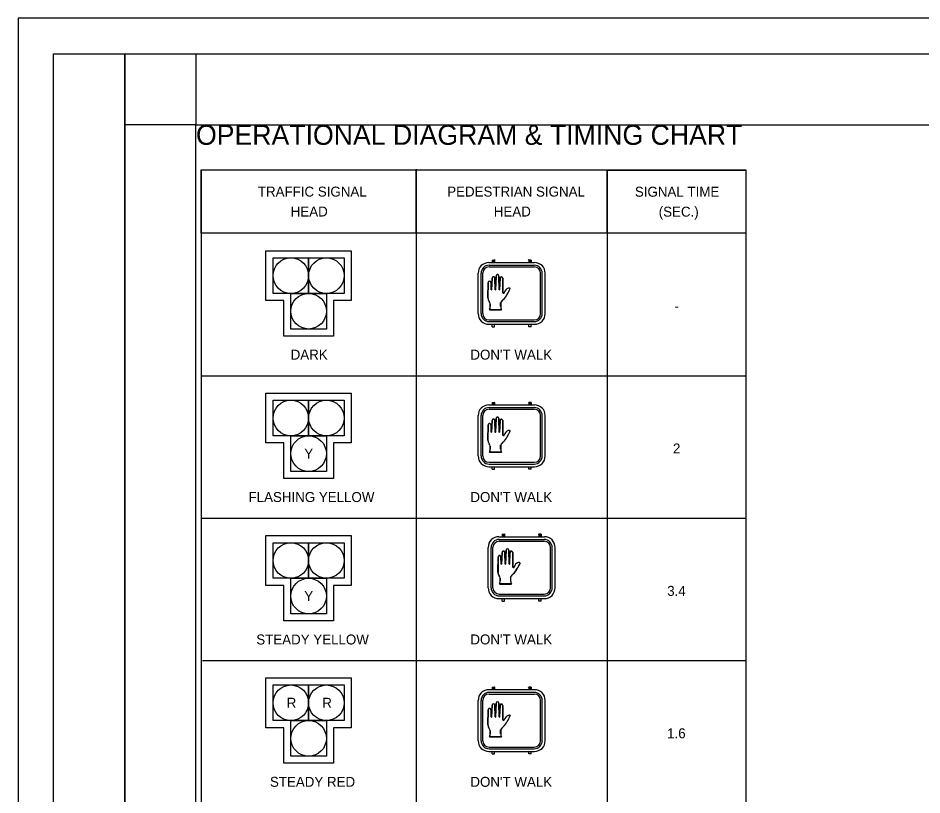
# Model space of a CAD drawing. Extents: x 59.9 to 93.9, y -8.4 to 13.6.
# Drawn here: x 59.95 to 72.65, y 2.7 to 13.61 of the extents above; entities that cross this region are included whole.
import ezdxf

# ---------------------------------------------------------------- set-up
doc = ezdxf.new("R2010")
doc.units = 0
for name, color, linetype in [('Default', 7, 'Continuous'), ('SG_P_Text', 7, 'Continuous'), ('SH_Border', 7, 'Continuous'), ('SH_Cut_Line', 7, 'Continuous'), ('SH_Data', 7, 'Continuous'), ('SH_Named_Boundary', 7, 'Continuous'), ('SH_Text', 7, 'Continuous')]:
    doc.layers.add(name, color=color, linetype=linetype)

# ---------------------------------------------------------------- blocks, each defined once
blk = doc.blocks.new('HAND')
at = {"layer": 'Default'}
for points in [[(-0.0196, 0.1047), (-0.0197, 0.1045), (-0.0167, 0.1665), (-0.0167, 0.1665)], [(-0.0022, 0.1665), (-0.0022, 0.1665), (-0.0014, 0.105), (-0.0014, 0.105)], [(0.0005, 0.1047), (0.0004, 0.1045), (0.004, 0.1776), (0.004, 0.1776)], [(0.0186, 0.1776), (0.0186, 0.1776), (0.0199, 0.105), (0.0199, 0.105)], [(0.0218, 0.1047), (0.0218, 0.1045), (0.0247, 0.1659), (0.0247, 0.1659)], [(0.0392, 0.1659), (0.0392, 0.1659), (0.0402, 0.0888), (0.0402, 0.0888)], [(-0.0387, 0.0626), (-0.0387, 0.0626), (-0.0372, 0.143), (-0.0372, 0.143)], [(-0.0227, 0.143), (-0.0227, 0.143), (-0.0215, 0.105), (-0.0215, 0.105)], [(0.0477, 0.089), (0.0477, 0.089)], [(-0.032, 0.0432), (-0.032, 0.0432)], [(-0.0271, 0.0154), (-0.0271, 0.0154), (-0.0271, 0.0308), (-0.0271, 0.0308)], [(0.0284, 0.0364), (0.0284, 0.0364), (0.0284, 0.0154), (0.0284, 0.0154)], [(0.0327, -0.0008), (-0.0313, -0.0008), (-0.0313, -0.0008)], [(0.0327, -0.0008), (0.0327, -0.0008)]]:
    blk.add_lwpolyline(points, dxfattribs=at)
for centre, radius, start, end in [((-0.03, 0.143), 0.00726, 0, 180), ((-0.0094, 0.1665), 0.00726, 0, 180), ((0.0113, 0.1776), 0.00726, 0, 180), ((0.032, 0.1659), 0.00726, 0, 180), ((-0.0206, 0.1048), 0.000943, 167.1401, 358.6099), ((-0.0005, 0.1048), 0.000943, 167.1401, 358.6099), ((0.0208, 0.1048), 0.000943, 167.1401, 358.6099), ((-0.1141, 0.1925), 0.2098, 318.2058, 337.3712), ((0.078, 0.0836), 0.0308, 107.2466, 169.8826), ((0.073, 0.1019), 0.0119, 56.229, 110.2726), ((-0.011, 0.0613), 0.0278, 177.3964, 220.6574), ((0.0742, 0.0112), 0.0523, 127.5194, 151.0809), ((0.0439, 0.0907), 0.00414, 208.0703, 335.996), ((-0.0476, 0.0298), 0.0205, 2.7749, 40.7212), ((-0.0593, 0.0151), 0.0322, 330.2887, 0.5181), ((0.0606, 0.0151), 0.0322, 179.4819, 209.7113)]:
    blk.add_arc(centre, radius, start, end, dxfattribs=at)

msp = doc.modelspace()

# ---------------------------------------------------------------- linework, layer by layer
at = {"layer": 'SG_P_Text'}
for p, q in [((62.52, 11.475), (70.174, 11.475)), ((62.52, 11.475), (62.52, -3.417)), ((65.54, 11.482), (65.54, -3.417)), ((68.226, 11.471), (68.226, -3.417)), ((70.171, 11.475), (70.171, -3.417)), ((62.534, 8.583), (70.178, 8.583)), ((62.523, 6.582), (70.178, 6.583)), ((62.541, 4.583), (70.177, 4.583))]:
    msp.add_line(p, q, dxfattribs=at)
for points in [[(62.52, 11.475), (65.54, 11.475), (65.54, 10.583), (62.52, 10.583)], [(65.54, 11.475), (68.226, 11.475), (68.226, 10.583), (65.54, 10.583)], [(68.226, 11.471), (70.172, 11.471), (70.172, 10.583), (68.226, 10.583)], [(63.43, 10.339), (64.63, 10.339), (64.63, 9.639), (64.38, 9.639), (64.38, 9.139), (63.68, 9.139), (63.68, 9.639), (63.43, 9.639)], [(63.53, 10.239), (64.03, 10.239), (64.03, 9.739), (63.53, 9.739)], [(64.03, 10.239), (64.53, 10.239), (64.53, 9.739), (64.03, 9.739)], [(63.78, 9.739), (64.28, 9.739), (64.28, 9.239), (63.78, 9.239)], [(63.43, 8.339), (64.63, 8.339), (64.63, 7.639), (64.38, 7.639), (64.38, 7.139), (63.68, 7.139), (63.68, 7.639), (63.43, 7.639)], [(63.53, 8.239), (64.03, 8.239), (64.03, 7.739), (63.53, 7.739)], [(64.03, 8.239), (64.53, 8.239), (64.53, 7.739), (64.03, 7.739)], [(63.78, 7.739), (64.28, 7.739), (64.28, 7.239), (63.78, 7.239)], [(63.43, 6.338), (64.63, 6.338), (64.63, 5.638), (64.38, 5.638), (64.38, 5.138), (63.68, 5.138), (63.68, 5.638), (63.43, 5.638)], [(63.53, 6.238), (64.03, 6.238), (64.03, 5.738), (63.53, 5.738)], [(64.03, 6.238), (64.53, 6.238), (64.53, 5.738), (64.03, 5.738)], [(63.78, 5.738), (64.28, 5.738), (64.28, 5.238), (63.78, 5.238)], [(63.43, 4.339), (64.63, 4.339), (64.63, 3.639), (64.38, 3.639), (64.38, 3.139), (63.68, 3.139), (63.68, 3.639), (63.43, 3.639)], [(63.53, 4.239), (64.03, 4.239), (64.03, 3.739), (63.53, 3.739)], [(64.03, 4.239), (64.53, 4.239), (64.53, 3.739), (64.03, 3.739)], [(63.78, 3.739), (64.28, 3.739), (64.28, 3.239), (63.78, 3.239)]]:
    msp.add_lwpolyline(points, close=True, dxfattribs=at)
for centre in [(63.78, 9.989), (64.28, 9.989), (64.03, 9.489), (63.78, 7.989), (64.28, 7.989), (64.03, 7.489), (63.78, 5.988), (64.28, 5.988), (64.03, 5.488), (63.78, 3.989), (64.28, 3.989), (64.03, 3.489)]:
    msp.add_circle(centre, 0.25, dxfattribs=at)
at = {"layer": 'SH_Border'}
for points in [[(60.448, 13.106), (61.448, 13.106), (61.448, -7.894), (60.448, -7.894)], [(61.448, 13.106), (93.448, 13.106), (93.448, -7.894), (61.448, -7.894)]]:
    msp.add_lwpolyline(points, close=True, dxfattribs=at)
at = {"layer": 'SH_Cut_Line'}
msp.add_lwpolyline([(59.948, -8.394), (93.948, -8.394), (93.948, 13.606), (59.948, 13.606)], close=True, dxfattribs=at)
at = {"layer": 'SH_Data'}
for p, q in [((66.563, 10.174), (66.606, 10.174)), ((66.618, 10.185), (66.603, 10.171)), ((66.603, 10.171), (66.605, 10.169)), ((66.62, 10.184), (66.605, 10.169)), ((66.607, 10.208), (66.607, 10.175)), ((66.607, 10.208), (66.641, 10.208)), ((66.61, 10.174), (67.156, 10.174)), ((66.631, 10.198), (66.645, 10.213)), ((66.633, 10.196), (66.647, 10.211)), ((66.643, 10.207), (66.643, 10.174)), ((66.647, 10.211), (66.645, 10.213)), ((67.121, 10.213), (67.119, 10.211)), ((67.133, 10.196), (67.119, 10.211)), ((67.135, 10.198), (67.121, 10.213)), ((67.123, 10.207), (67.123, 10.174)), ((67.159, 10.208), (67.125, 10.208)), ((67.146, 10.184), (67.161, 10.169)), ((67.148, 10.185), (67.163, 10.171)), ((67.159, 10.208), (67.159, 10.175)), ((67.16, 10.174), (67.203, 10.174)), ((67.163, 10.171), (67.161, 10.169)), ((66.566, 10.136), (67.2, 10.136)), ((66.566, 10.111), (67.2, 10.111)), ((66.412, 9.456), (66.412, 10.022)), ((66.453, 9.456), (66.453, 10.022)), ((66.477, 9.755), (66.477, 10.022)), ((67.289, 9.755), (67.289, 10.022)), ((67.313, 9.456), (67.313, 10.022)), ((67.354, 9.456), (67.354, 10.022)), ((66.477, 9.456), (66.477, 9.755)), ((67.289, 9.456), (67.289, 9.755)), ((66.563, 9.305), (67.203, 9.305)), ((66.566, 9.367), (67.2, 9.367)), ((66.566, 9.343), (67.2, 9.343)), ((66.607, 9.27), (66.607, 9.305)), ((66.607, 9.27), (66.643, 9.27)), ((66.643, 9.27), (66.643, 9.305)), ((67.123, 9.27), (67.123, 9.305)), ((67.159, 9.27), (67.123, 9.27)), ((67.159, 9.27), (67.159, 9.305)), ((66.563, 8.174), (66.606, 8.174)), ((66.566, 8.136), (67.2, 8.136)), ((66.618, 8.185), (66.603, 8.171)), ((66.603, 8.171), (66.605, 8.169)), ((66.62, 8.184), (66.605, 8.169)), ((66.607, 8.208), (66.607, 8.175)), ((66.607, 8.208), (66.641, 8.208)), ((66.61, 8.174), (67.156, 8.174)), ((66.631, 8.198), (66.645, 8.213)), ((66.633, 8.196), (66.647, 8.211)), ((66.643, 8.207), (66.643, 8.174)), ((66.647, 8.211), (66.645, 8.213)), ((67.121, 8.213), (67.119, 8.211)), ((67.133, 8.196), (67.119, 8.211)), ((67.135, 8.198), (67.121, 8.213)), ((67.123, 8.207), (67.123, 8.174)), ((67.159, 8.208), (67.125, 8.208)), ((67.146, 8.184), (67.161, 8.169)), ((67.148, 8.185), (67.163, 8.171)), ((67.159, 8.208), (67.159, 8.175)), ((67.16, 8.174), (67.203, 8.174)), ((67.163, 8.171), (67.161, 8.169)), ((66.412, 7.456), (66.412, 8.022)), ((66.453, 7.456), (66.453, 8.022)), ((66.477, 7.755), (66.477, 8.022)), ((66.566, 8.111), (67.2, 8.111)), ((67.289, 7.755), (67.289, 8.022)), ((67.313, 7.456), (67.313, 8.022)), ((67.354, 7.456), (67.354, 8.022)), ((66.477, 7.456), (66.477, 7.755)), ((67.289, 7.456), (67.289, 7.755)), ((66.566, 7.367), (67.2, 7.367)), ((66.563, 7.305), (67.203, 7.305)), ((66.566, 7.343), (67.2, 7.343)), ((66.607, 7.27), (66.607, 7.305)), ((66.607, 7.27), (66.643, 7.27)), ((66.643, 7.27), (66.643, 7.305)), ((67.123, 7.27), (67.123, 7.305)), ((67.159, 7.27), (67.123, 7.27)), ((67.159, 7.27), (67.159, 7.305)), ((66.748, 6.356), (66.748, 6.322)), ((66.748, 6.356), (66.781, 6.356)), ((66.771, 6.346), (66.786, 6.36)), ((66.773, 6.344), (66.788, 6.359)), ((66.784, 6.355), (66.784, 6.321)), ((66.788, 6.359), (66.786, 6.36)), ((67.261, 6.36), (67.259, 6.359)), ((67.274, 6.344), (67.259, 6.359)), ((67.276, 6.346), (67.261, 6.36)), ((67.263, 6.355), (67.263, 6.321)), ((67.299, 6.356), (67.266, 6.356)), ((67.299, 6.356), (67.299, 6.322)), ((66.703, 6.321), (66.747, 6.321)), ((66.707, 6.283), (67.34, 6.283)), ((66.707, 6.259), (67.34, 6.259)), ((66.758, 6.333), (66.744, 6.318)), ((66.744, 6.318), (66.746, 6.317)), ((66.76, 6.331), (66.746, 6.317)), ((66.75, 6.321), (67.297, 6.321)), ((67.287, 6.331), (67.301, 6.317)), ((67.288, 6.333), (67.303, 6.318)), ((67.3, 6.321), (67.343, 6.321)), ((67.303, 6.318), (67.301, 6.317)), ((66.552, 5.604), (66.552, 6.17)), ((66.593, 5.604), (66.593, 6.17)), ((66.618, 5.903), (66.618, 6.17)), ((67.429, 5.903), (67.429, 6.17)), ((67.453, 5.604), (67.453, 6.17)), ((67.495, 5.604), (67.495, 6.17)), ((66.618, 5.604), (66.618, 5.903)), ((67.429, 5.604), (67.429, 5.903)), ((66.707, 5.515), (67.34, 5.515)), ((66.707, 5.491), (67.34, 5.491)), ((66.703, 5.453), (67.343, 5.453)), ((66.748, 5.418), (66.748, 5.453)), ((66.748, 5.418), (66.784, 5.418)), ((66.784, 5.418), (66.784, 5.453)), ((67.263, 5.418), (67.263, 5.453)), ((67.299, 5.418), (67.263, 5.418)), ((67.299, 5.418), (67.299, 5.453)), ((66.607, 4.208), (66.607, 4.175)), ((66.607, 4.208), (66.641, 4.208)), ((66.631, 4.198), (66.645, 4.213)), ((66.633, 4.196), (66.647, 4.211)), ((66.643, 4.207), (66.643, 4.174)), ((66.647, 4.211), (66.645, 4.213)), ((67.121, 4.213), (67.119, 4.211)), ((67.133, 4.196), (67.119, 4.211)), ((67.135, 4.198), (67.121, 4.213)), ((67.123, 4.207), (67.123, 4.174)), ((67.159, 4.208), (67.125, 4.208)), ((67.159, 4.208), (67.159, 4.175)), ((66.563, 4.174), (66.606, 4.174)), ((66.566, 4.136), (67.2, 4.136)), ((66.566, 4.111), (67.2, 4.111)), ((66.618, 4.185), (66.603, 4.171)), ((66.603, 4.171), (66.605, 4.169)), ((66.62, 4.184), (66.605, 4.169)), ((66.61, 4.174), (67.156, 4.174)), ((67.146, 4.184), (67.161, 4.169)), ((67.148, 4.185), (67.163, 4.171)), ((67.16, 4.174), (67.203, 4.174)), ((67.163, 4.171), (67.161, 4.169)), ((66.412, 3.456), (66.412, 4.022)), ((66.453, 3.456), (66.453, 4.022)), ((66.477, 3.755), (66.477, 4.022)), ((67.289, 3.755), (67.289, 4.022)), ((67.313, 3.456), (67.313, 4.022)), ((67.354, 3.456), (67.354, 4.022)), ((66.477, 3.456), (66.477, 3.755)), ((67.289, 3.456), (67.289, 3.755)), ((66.563, 3.305), (67.203, 3.305)), ((66.566, 3.367), (67.2, 3.367)), ((66.566, 3.343), (67.2, 3.343)), ((66.607, 3.27), (66.607, 3.305)), ((66.643, 3.27), (66.643, 3.305)), ((67.123, 3.27), (67.123, 3.305)), ((67.159, 3.27), (67.159, 3.305)), ((66.607, 3.27), (66.643, 3.27)), ((67.159, 3.27), (67.123, 3.27))]:
    msp.add_line(p, q, dxfattribs=at)
for points in [[(66.609, 9.954), (66.601, 9.79), (66.601, 9.79)], [(66.649, 9.79), (66.647, 9.954), (66.647, 9.954)], [(66.664, 9.983), (66.654, 9.79), (66.654, 9.79)], [(66.706, 9.79), (66.702, 9.983)], [(66.719, 9.952), (66.711, 9.79), (66.711, 9.79)], [(66.76, 9.747), (66.757, 9.952)], [(66.554, 9.891), (66.55, 9.678)], [(66.596, 9.79), (66.593, 9.891), (66.593, 9.891)], [(66.601, 9.789), (66.601, 9.789), (66.601, 9.789)], [(66.654, 9.789), (66.654, 9.789), (66.654, 9.789)], [(66.711, 9.789), (66.711, 9.789), (66.711, 9.789)], [(66.779, 9.748), (66.779, 9.748)], [(66.568, 9.627), (66.568, 9.627)], [(66.581, 9.594), (66.581, 9.553)], [(66.728, 9.553), (66.728, 9.609)], [(66.57, 9.51), (66.74, 9.51)], [(66.554, 7.891), (66.55, 7.678)], [(66.596, 7.79), (66.593, 7.891), (66.593, 7.891)], [(66.609, 7.954), (66.601, 7.79), (66.601, 7.79)], [(66.649, 7.79), (66.647, 7.954), (66.647, 7.954)], [(66.664, 7.983), (66.654, 7.79), (66.654, 7.79)], [(66.706, 7.79), (66.702, 7.983)], [(66.719, 7.952), (66.711, 7.79), (66.711, 7.79)], [(66.76, 7.747), (66.757, 7.952)], [(66.601, 7.789), (66.601, 7.789), (66.601, 7.789)], [(66.654, 7.789), (66.654, 7.789), (66.654, 7.789)], [(66.711, 7.789), (66.711, 7.789), (66.711, 7.789)], [(66.779, 7.748), (66.779, 7.748)], [(66.568, 7.627), (66.568, 7.627)], [(66.57, 7.51), (66.74, 7.51)], [(66.581, 7.594), (66.581, 7.553)], [(66.728, 7.553), (66.728, 7.609)], [(66.749, 6.101), (66.741, 5.937), (66.741, 5.937)], [(66.79, 5.938), (66.787, 6.101), (66.788, 6.101)], [(66.804, 6.131), (66.795, 5.937), (66.795, 5.937)], [(66.846, 5.938), (66.843, 6.131)], [(66.859, 6.1), (66.851, 5.937), (66.851, 5.937)], [(66.9, 5.895), (66.897, 6.1)], [(66.695, 6.039), (66.691, 5.826)], [(66.736, 5.938), (66.733, 6.039), (66.733, 6.039)], [(66.741, 5.937), (66.741, 5.937), (66.741, 5.937)], [(66.795, 5.937), (66.795, 5.937), (66.794, 5.937)], [(66.851, 5.937), (66.851, 5.937), (66.851, 5.937)], [(66.92, 5.896), (66.92, 5.896)], [(66.708, 5.774), (66.708, 5.774)], [(66.721, 5.741), (66.721, 5.701)], [(66.869, 5.701), (66.869, 5.756)], [(66.71, 5.657), (66.88, 5.657)], [(66.609, 3.954), (66.601, 3.79), (66.601, 3.79)], [(66.649, 3.79), (66.647, 3.954), (66.647, 3.954)], [(66.664, 3.983), (66.654, 3.79), (66.654, 3.79)], [(66.706, 3.79), (66.702, 3.983)], [(66.719, 3.952), (66.711, 3.79), (66.711, 3.79)], [(66.76, 3.747), (66.757, 3.952)], [(66.554, 3.891), (66.55, 3.678)], [(66.596, 3.79), (66.593, 3.891), (66.593, 3.891)], [(66.601, 3.789), (66.601, 3.789), (66.601, 3.789)], [(66.654, 3.789), (66.654, 3.789), (66.654, 3.789)], [(66.711, 3.789), (66.711, 3.789), (66.711, 3.789)], [(66.779, 3.748), (66.779, 3.748)], [(66.568, 3.627), (66.568, 3.627)], [(66.581, 3.594), (66.581, 3.553)], [(66.728, 3.553), (66.728, 3.609)], [(66.57, 3.51), (66.74, 3.51)]]:
    msp.add_lwpolyline(points, dxfattribs=at)
for centre in [(66.625, 10.191), (67.141, 10.191), (66.625, 8.191), (67.141, 8.191), (66.766, 6.338), (67.281, 6.338), (66.625, 4.191), (67.141, 4.191)]:
    msp.add_circle(centre, 0.00918, dxfattribs=at)
for centre, radius, start, end in [((66.563, 10.022), 0.151, 90, 180), ((67.203, 10.022), 0.151, 360, 90), ((66.566, 10.022), 0.113, 90, 180), ((66.566, 10.022), 0.089, 90, 180), ((67.2, 10.022), 0.113, 360, 90), ((67.2, 10.022), 0.089, 360, 90), ((66.573, 9.891), 0.0193, 0, 180), ((66.628, 9.954), 0.0193, 0, 180), ((66.683, 9.983), 0.0193, 360, 180), ((66.738, 9.952), 0.0193, 0, 180), ((66.598, 9.79), 0.0025, 167.1401, 346.8691), ((66.598, 9.79), 0.0025, 347.3062, 358.6099), ((66.652, 9.79), 0.0025, 167.1401, 346.5951), ((66.652, 9.79), 0.0025, 351.0095, 358.6099), ((66.708, 9.79), 0.0025, 167.1401, 347.1404), ((66.708, 9.79), 0.0025, 349.4624, 358.6099), ((66.35, 10.023), 0.557, 318.2058, 337.3712), ((66.86, 9.734), 0.0817, 107.2466, 169.8826), ((66.847, 9.782), 0.0315, 56.229, 110.2726), ((66.624, 9.675), 0.0738, 177.3964, 220.6574), ((66.85, 9.542), 0.139, 127.5194, 151.0809), ((66.769, 9.753), 0.011, 208.0703, 335.996), ((66.527, 9.591), 0.0544, 2.7749, 40.7212), ((66.496, 9.552), 0.0855, 330.2887, 0.5181), ((66.814, 9.552), 0.0855, 179.4819, 209.7113), ((66.563, 9.456), 0.151, 180, 270), ((66.566, 9.456), 0.113, 180, 270), ((66.566, 9.456), 0.089, 180, 270), ((67.2, 9.456), 0.113, 270, 360), ((67.2, 9.456), 0.089, 270, 360), ((67.203, 9.456), 0.151, 270, 360), ((66.563, 8.022), 0.151, 90, 180), ((66.566, 8.022), 0.113, 90, 180), ((67.2, 8.022), 0.113, 360, 90), ((67.203, 8.022), 0.151, 360, 90), ((66.566, 8.022), 0.089, 90, 180), ((66.683, 7.983), 0.0193, 360, 180), ((67.2, 8.022), 0.089, 360, 90), ((66.573, 7.891), 0.0193, 0, 180), ((66.628, 7.954), 0.0193, 0, 180), ((66.738, 7.952), 0.0193, 0, 180), ((66.598, 7.79), 0.0025, 167.1401, 346.8691), ((66.598, 7.79), 0.0025, 347.3062, 358.6099), ((66.652, 7.79), 0.0025, 167.1401, 346.5951), ((66.652, 7.79), 0.0025, 351.0095, 358.6099), ((66.708, 7.79), 0.0025, 167.1401, 347.1404), ((66.708, 7.79), 0.0025, 349.4624, 358.6099), ((66.769, 7.753), 0.011, 208.0703, 335.996), ((66.35, 8.023), 0.557, 318.2058, 337.3712), ((66.86, 7.734), 0.0817, 107.2466, 169.8826), ((66.847, 7.782), 0.0315, 56.229, 110.2726), ((66.624, 7.675), 0.0738, 177.3964, 220.6574), ((66.527, 7.591), 0.0544, 2.7749, 40.7212), ((66.85, 7.542), 0.139, 127.5194, 151.0809), ((66.496, 7.552), 0.0855, 330.2887, 0.5181), ((66.814, 7.552), 0.0855, 179.4819, 209.7113), ((66.563, 7.456), 0.151, 180, 270), ((66.566, 7.456), 0.113, 180, 270), ((66.566, 7.456), 0.089, 180, 270), ((67.2, 7.456), 0.113, 270, 360), ((67.2, 7.456), 0.089, 270, 360), ((67.203, 7.456), 0.151, 270, 360), ((66.703, 6.17), 0.151, 90, 180), ((66.707, 6.17), 0.113, 90, 180), ((66.707, 6.17), 0.089, 90, 180), ((67.34, 6.17), 0.113, 360, 90), ((67.34, 6.17), 0.089, 360, 90), ((67.343, 6.17), 0.151, 360, 90), ((66.768, 6.101), 0.0193, 0, 180), ((66.823, 6.131), 0.0193, 360, 180), ((66.878, 6.1), 0.0193, 0, 180), ((66.714, 6.039), 0.0193, 0, 180), ((66.739, 5.937), 0.0025, 167.1401, 346.8691), ((66.739, 5.937), 0.0025, 347.3062, 358.6099), ((66.792, 5.937), 0.0025, 167.1401, 346.5951), ((66.792, 5.937), 0.0025, 351.0095, 358.6099), ((66.849, 5.937), 0.0025, 167.1401, 347.1404), ((66.849, 5.937), 0.0025, 349.4624, 358.6099), ((66.91, 5.9), 0.011, 208.0703, 335.996), ((66.491, 6.17), 0.557, 318.2058, 337.3712), ((67, 5.881), 0.0817, 107.2466, 169.8826), ((66.987, 5.93), 0.0315, 56.229, 110.2726), ((66.764, 5.822), 0.0738, 177.3964, 220.6574), ((66.667, 5.739), 0.0544, 2.7749, 40.7212), ((66.99, 5.689), 0.139, 127.5194, 151.0809), ((66.703, 5.604), 0.151, 180, 270), ((66.707, 5.604), 0.113, 180, 270), ((66.707, 5.604), 0.089, 180, 270), ((66.636, 5.7), 0.0855, 330.2887, 0.5181), ((66.954, 5.7), 0.0855, 179.4819, 209.7113), ((67.34, 5.604), 0.113, 270, 360), ((67.34, 5.604), 0.089, 270, 360), ((67.343, 5.604), 0.151, 270, 360), ((66.563, 4.022), 0.151, 90, 180), ((66.566, 4.022), 0.113, 90, 180), ((66.566, 4.022), 0.089, 90, 180), ((67.2, 4.022), 0.113, 360, 90), ((67.2, 4.022), 0.089, 360, 90), ((67.203, 4.022), 0.151, 360, 90), ((66.628, 3.954), 0.0193, 0, 180), ((66.683, 3.983), 0.0193, 360, 180), ((66.738, 3.952), 0.0193, 0, 180), ((66.573, 3.891), 0.0193, 0, 180), ((66.86, 3.734), 0.0817, 107.2466, 169.8826), ((66.847, 3.782), 0.0315, 56.229, 110.2726), ((66.598, 3.79), 0.0025, 167.1401, 346.8691), ((66.598, 3.79), 0.0025, 347.3062, 358.6099), ((66.652, 3.79), 0.0025, 167.1401, 346.5951), ((66.652, 3.79), 0.0025, 351.0095, 358.6099), ((66.708, 3.79), 0.0025, 167.1401, 347.1404), ((66.708, 3.79), 0.0025, 349.4624, 358.6099), ((66.769, 3.753), 0.011, 208.0703, 335.996), ((66.35, 4.023), 0.557, 318.2058, 337.3712), ((66.624, 3.675), 0.0738, 177.3964, 220.6574), ((66.527, 3.591), 0.0544, 2.7749, 40.7212), ((66.85, 3.542), 0.139, 127.5194, 151.0809), ((66.563, 3.456), 0.151, 180, 270), ((66.566, 3.456), 0.113, 180, 270), ((66.566, 3.456), 0.089, 180, 270), ((66.496, 3.552), 0.0855, 330.2887, 0.5181), ((66.814, 3.552), 0.0855, 179.4819, 209.7113), ((67.2, 3.456), 0.113, 270, 360), ((67.2, 3.456), 0.089, 270, 360), ((67.203, 3.456), 0.151, 270, 360)]:
    msp.add_arc(centre, radius, start, end, dxfattribs=at)
at = {"layer": 'SH_Named_Boundary'}
for points in [[(61.448, 13.106), (62.448, 13.106), (62.448, 12.106), (61.448, 12.106)], [(62.448, 12.106), (90.948, 12.106), (90.948, -6.894), (62.448, -6.894)]]:
    msp.add_lwpolyline(points, close=True, dxfattribs=at)

# ---------------------------------------------------------------- block references
at = {"layer": 'SH_Data', "xscale": 2.6528245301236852, "yscale": 2.6528245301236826, "rotation": -4.132614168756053e-09}
for p in [(66.653, 9.512), (66.653, 7.512), (66.793, 5.66), (66.653, 3.512)]:
    msp.add_blockref('HAND', p, dxfattribs=at)

# ---------------------------------------------------------------- texts
at = {"layer": 'Default'}
for s, p in [('TRAFFIC SIGNAL', (63.317, 11.099)), ('PEDESTRIAN SIGNAL', (65.977, 11.099)), ('SIGNAL TIME', (68.614, 11.097)), ('HEAD', (63.779, 10.819)), ('HEAD', (66.632, 10.819)), ('(SEC.)', (68.949, 10.817)), ('-', (69.169, 9.491)), ('2', (69.149, 7.491)), ('3.4', (69.068, 5.491)), ('1.6', (69.067, 3.491))]:
    msp.add_text(s, height=0.14, dxfattribs=at).set_placement(p)
at = {"layer": 'SG_P_Text'}
for s, height, p in [('OPERATIONAL DIAGRAM & TIMING CHART', 0.28, (62.448, 11.826)), ('Y', 0.14, (63.969, 7.419)), ('Y', 0.14, (63.969, 5.418)), ('R', 0.14, (63.722, 3.919)), ('R', 0.14, (64.222, 3.919))]:
    msp.add_text(s, height=height, dxfattribs=at).set_placement(p)
at = {"layer": 'SH_Text'}
for s, p in [('DARK', (63.778, 8.809)), ("DON'T WALK", (66.303, 8.809)), ('FLASHING YELLOW', (63.186, 6.809)), ("DON'T WALK", (66.303, 6.809)), ('STEADY YELLOW', (63.295, 4.808)), ("DON'T WALK", (66.303, 4.809)), ('STEADY RED', (63.487, 2.809)), ("DON'T WALK", (66.303, 2.809))]:
    msp.add_text(s, height=0.14, rotation=360, dxfattribs=at).set_placement(p)

doc.saveas('drawing.dxf')
